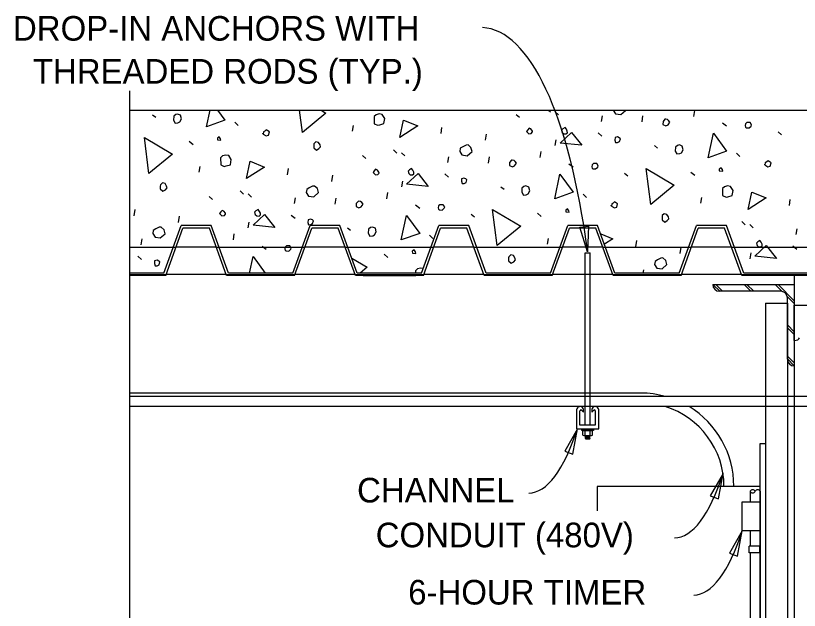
# Model space of a CAD drawing. Extents: x 927736.2 to 927809.6, y 636703.6 to 636757.7.
# Drawn here: x 927784.6 to 927796.47, y 636748.62 to 636757.62 of the extents above; entities that cross this region are included whole.
import ezdxf

# ---------------------------------------------------------------- set-up
doc = ezdxf.new("R2010")
doc.units = 0
for name, color, linetype in [('Default', 7, 'Continuous'), ('DimLines_dp', 7, 'Continuous'), ('Miscellaneous1', 7, 'Continuous'), ('Miscellaneous2', 7, 'Continuous'), ('Miscellaneous3', 7, 'Continuous')]:
    doc.layers.add(name, color=color, linetype=linetype)

msp = doc.modelspace()

# ---------------------------------------------------------------- linework, layer by layer
at = {"layer": 'Default'}
msp.add_line((927795.875, 636749.822), (927795.875, 636743.545), dxfattribs=at)
at = {"layer": 'DimLines_dp'}
msp.add_lwpolyline([(927786.333, 636737.782), (927786.333, 636747.055), (927786.142, 636747.055), (927786.333, 636747.139), (927786.524, 636747.222), (927786.333, 636747.222), (927786.333, 636756.484)], dxfattribs=at)
for points in [[(927793.262, 636754.047), (927793.144, 636754.42), (927793.273, 636754.438)], [(927793.108, 636751.368), (927792.915, 636751.028), (927793.038, 636750.984)], [(927795.311, 636750.689), (927795.118, 636750.349), (927795.241, 636750.305)], [(927795.602, 636749.822), (927795.409, 636749.483), (927795.532, 636749.438)]]:
    msp.add_lwpolyline(points, close=True, dxfattribs=at)
for centre, major_axis, ratio, start_param, end_param in [((927791.283, 636750.246), (-0.388, -7.199), 0.2923, 2.142822, 3.141563), ((927792.341, 636754.506), (-0.032, 4.113), 0.280094, 3.141615, 3.84244), ((927794.544, 636753.827), (-0.032, 4.113), 0.280094, 3.141615, 3.84244), ((927794.835, 636752.961), (-0.032, 4.113), 0.280094, 3.141615, 3.84244)]:
    msp.add_ellipse(centre, major_axis=major_axis, ratio=ratio, start_param=start_param, end_param=end_param, dxfattribs=at)
at = {"layer": 'Miscellaneous1'}
for p, q in [((927794.065, 636751.907), (927786.333, 636751.907)), ((927795.952, 636751.856), (927786.333, 636751.856)), ((927797.417, 636751.856), (927795.952, 636751.856)), ((927795.952, 636751.702), (927786.333, 636751.702)), ((927793.095, 636751.651), (927793.095, 636751.368)), ((927793.146, 636751.419), (927793.146, 636751.639)), ((927793.168, 636751.648), (927793.198, 636751.618)), ((927793.198, 636751.663), (927793.192, 636751.673)), ((927793.198, 636751.618), (927793.198, 636751.663)), ((927793.332, 636751.673), (927793.326, 636751.663)), ((927793.326, 636751.663), (927793.326, 636751.618)), ((927793.326, 636751.618), (927793.356, 636751.648)), ((927793.378, 636751.639), (927793.378, 636751.419)), ((927793.429, 636751.368), (927793.429, 636751.651)), ((927797.417, 636751.702), (927795.952, 636751.702)), ((927793.378, 636751.419), (927793.146, 636751.419)), ((927793.095, 636751.368), (927793.429, 636751.368)), ((927795.721, 636750.42), (927795.721, 636750.262)), ((927795.875, 636750.42), (927795.875, 636750.262)), ((927795.875, 636749.822), (927795.875, 636750.262)), ((927795.721, 636749.822), (927795.721, 636749.588)), ((927795.721, 636749.485), (927795.721, 636744.78))]:
    msp.add_line(p, q, dxfattribs=at)
msp.add_lwpolyline([(927795.875, 636743.771), (927795.875, 636750.493), (927793.408, 636750.493), (927793.408, 636750.124)], dxfattribs=at)
msp.add_lwpolyline([(927795.602, 636750.262), (927795.875, 636750.262), (927795.875, 636749.822), (927795.602, 636749.822)], close=True, dxfattribs=at)
for centre, radius, start, end in [((927794.065, 636750.497), 1.41, 74.4971, 90), ((927793.146, 636751.651), 0.0513, 26.1794, 179.9999), ((927793.159, 636751.639), 0.0128, 45, 180), ((927793.378, 636751.651), 0.0513, 0.0001, 153.8206), ((927793.365, 636751.639), 0.0128, 360, 135), ((927794.065, 636750.497), 1.26, 0, 72.9364), ((927794.065, 636750.497), 1.41, 0, 58.6817), ((927795.759, 636750.398), 0.0441, 29.0027, 150.9974), ((927795.836, 636750.398), 0.0441, 29.0028, 150.9973), ((927795.759, 636750.441), 0.0441, 209.003, 330.9971)]:
    msp.add_arc(centre, radius, start, end, dxfattribs=at)
at = {"layer": 'Miscellaneous2'}
for p, q in [((927786.333, 636756.193), (927803.622, 636756.193)), ((927786.677, 636756.123), (927786.725, 636756.085)), ((927792.178, 636756.129), (927792.228, 636756.085)), ((927792.67, 636756.193), (927792.698, 636756.166)), ((927792.767, 636756.172), (927792.819, 636756.122)), ((927794.868, 636756.096), (927794.882, 636756.189)), ((927787.92, 636756.009), (927787.972, 636755.959)), ((927793.471, 636756.022), (927793.486, 636756.109)), ((927794.086, 636756.014), (927794.099, 636756.107)), ((927795.302, 636756.002), (927795.366, 636755.955)), ((927789.705, 636755.875), (927789.72, 636755.962)), ((927791.043, 636755.838), (927791.057, 636755.931)), ((927791.715, 636755.737), (927791.729, 636755.83)), ((927793.422, 636755.849), (927793.479, 636755.801)), ((927796.144, 636755.864), (927796.194, 636755.819)), ((927787.231, 636755.723), (927787.289, 636755.674)), ((927792.771, 636755.656), (927792.786, 636755.743)), ((927794.272, 636755.656), (927794.32, 636755.617)), ((927790.324, 636755.594), (927790.375, 636755.544)), ((927790.444, 636755.549), (927790.496, 636755.499)), ((927792.545, 636755.474), (927792.559, 636755.567)), ((927795.515, 636755.542), (927795.567, 636755.492)), ((927789.855, 636755.506), (927789.905, 636755.462)), ((927791.148, 636755.4), (927791.163, 636755.487)), ((927791.763, 636755.392), (927791.776, 636755.485)), ((927787.382, 636755.252), (927787.397, 636755.339)), ((927788.72, 636755.215), (927788.734, 636755.308)), ((927792.979, 636755.379), (927793.043, 636755.333)), ((927789.392, 636755.114), (927789.406, 636755.207)), ((927791.099, 636755.227), (927791.156, 636755.178)), ((927793.821, 636755.241), (927793.871, 636755.197)), ((927794.826, 636755.255), (927794.883, 636755.207)), ((927790.448, 636755.033), (927790.463, 636755.12)), ((927788, 636754.971), (927788.052, 636754.921)), ((927790.222, 636754.851), (927790.236, 636754.944)), ((927791.948, 636755.033), (927791.997, 636754.995)), ((927787.532, 636754.884), (927787.582, 636754.84)), ((927788.121, 636754.927), (927788.173, 636754.877)), ((927788.825, 636754.777), (927788.84, 636754.864)), ((927789.44, 636754.769), (927789.453, 636754.862)), ((927793.192, 636754.919), (927793.244, 636754.869)), ((927794.977, 636754.785), (927794.992, 636754.872)), ((927796.315, 636754.748), (927796.329, 636754.84)), ((927790.656, 636754.757), (927790.72, 636754.71)), ((927786.397, 636754.593), (927786.411, 636754.686)), ((927787.069, 636754.492), (927787.083, 636754.585)), ((927788.775, 636754.604), (927788.833, 636754.556)), ((927791.498, 636754.619), (927791.548, 636754.575)), ((927792.503, 636754.633), (927792.56, 636754.584)), ((927788.125, 636754.411), (927788.14, 636754.498)), ((927795.595, 636754.504), (927795.647, 636754.454)), ((927795.716, 636754.459), (927795.767, 636754.409)), ((927786.849, 636753.726), (927787.111, 636754.446)), ((927786.876, 636753.688), (927787.137, 636754.407)), ((927787.563, 636754.446), (927787.111, 636754.446)), ((927787.536, 636754.407), (927787.137, 636754.407)), ((927787.798, 636753.688), (927787.536, 636754.407)), ((927787.825, 636753.726), (927787.563, 636754.446)), ((927788.798, 636753.726), (927789.06, 636754.446)), ((927788.825, 636753.688), (927789.087, 636754.407)), ((927789.512, 636754.446), (927789.06, 636754.446)), ((927789.485, 636754.407), (927789.087, 636754.407)), ((927789.747, 636753.688), (927789.485, 636754.407)), ((927789.774, 636753.726), (927789.512, 636754.446)), ((927789.625, 636754.411), (927789.674, 636754.373)), ((927790.748, 636753.726), (927791.01, 636754.446)), ((927790.775, 636753.688), (927791.037, 636754.407)), ((927791.462, 636754.446), (927791.01, 636754.446)), ((927791.435, 636754.407), (927791.037, 636754.407)), ((927791.697, 636753.688), (927791.435, 636754.407)), ((927791.724, 636753.726), (927791.462, 636754.446)), ((927792.698, 636753.726), (927792.96, 636754.446)), ((927792.725, 636753.688), (927792.987, 636754.407)), ((927793.412, 636754.446), (927792.96, 636754.446)), ((927793.385, 636754.407), (927792.987, 636754.407)), ((927793.647, 636753.688), (927793.385, 636754.407)), ((927793.674, 636753.726), (927793.412, 636754.446)), ((927794.648, 636753.726), (927794.91, 636754.446)), ((927794.675, 636753.688), (927794.936, 636754.407)), ((927795.362, 636754.446), (927794.91, 636754.446)), ((927795.335, 636754.407), (927794.936, 636754.407)), ((927795.597, 636753.688), (927795.335, 636754.407)), ((927795.624, 636753.726), (927795.362, 636754.446)), ((927796.42, 636754.309), (927796.435, 636754.397)), ((927786.502, 636754.155), (927786.517, 636754.242)), ((927787.899, 636754.229), (927787.913, 636754.322)), ((927790.869, 636754.297), (927790.921, 636754.247)), ((927792.654, 636754.162), (927792.669, 636754.249)), ((927788.333, 636754.135), (927788.397, 636754.088)), ((927793.992, 636754.125), (927794.005, 636754.218)), ((927794.664, 636754.024), (927794.677, 636754.117)), ((927796.37, 636754.137), (927796.428, 636754.088)), ((927786.452, 636753.982), (927786.51, 636753.933)), ((927790.18, 636754.01), (927790.237, 636753.962)), ((927795.72, 636753.943), (927795.735, 636754.03)), ((927794.103, 636753.726), (927794.112, 636753.774)), ((927786.849, 636753.726), (927786.333, 636753.726)), ((927786.876, 636753.688), (927786.333, 636753.688)), ((927788.825, 636753.688), (927787.798, 636753.688)), ((927788.798, 636753.726), (927787.825, 636753.726)), ((927790.775, 636753.688), (927789.747, 636753.688)), ((927790.748, 636753.726), (927789.774, 636753.726)), ((927789.863, 636753.688), (927790.659, 636753.688)), ((927792.725, 636753.688), (927791.697, 636753.688)), ((927792.698, 636753.726), (927791.724, 636753.726)), ((927792.622, 636753.688), (927791.8, 636753.688)), ((927794.675, 636753.688), (927793.647, 636753.688)), ((927794.648, 636753.726), (927793.674, 636753.726)), ((927796.624, 636753.688), (927795.597, 636753.688)), ((927796.597, 636753.726), (927795.624, 636753.726))]:
    msp.add_line(p, q, dxfattribs=at)
for points in [[(927786.996, 636756.1), (927786.992, 636756.042), (927787.017, 636755.997), (927787.06, 636756.002), (927787.088, 636756.016), (927787.115, 636756.062), (927787.1, 636756.115), (927787.056, 636756.135), (927787.027, 636756.127), (927786.996, 636756.1)], [(927787.492, 636755.939), (927787.546, 636756.193)], [(927787.659, 636756.193), (927787.772, 636756.04), (927787.492, 636755.939)], [(927788.944, 636755.856), (927788.902, 636756.193)], [(927789.226, 636756.193), (927789.3, 636756.149), (927788.944, 636755.856)], [(927790.029, 636756.096), (927790.033, 636755.988), (927790.084, 636755.964), (927790.114, 636755.971), (927790.179, 636755.989), (927790.19, 636756.069), (927790.154, 636756.129), (927790.108, 636756.136), (927790.06, 636756.123), (927790.029, 636756.096)], [(927793.649, 636756.191), (927793.683, 636756.136), (927793.762, 636756.126), (927793.835, 636756.19), (927793.834, 636756.193)], [(927793.649, 636756.193), (927793.649, 636756.191)], [(927790.421, 636755.779), (927790.477, 636756.043), (927790.693, 636755.954), (927790.421, 636755.779)], [(927794.403, 636756.023), (927794.402, 636755.978), (927794.446, 636755.958), (927794.48, 636755.973), (927794.508, 636756.013), (927794.488, 636756.039), (927794.471, 636756.054), (927794.444, 636756.059), (927794.432, 636756.056), (927794.403, 636756.023)], [(927795.652, 636755.936), (927795.667, 636755.927), (927795.706, 636755.925), (927795.737, 636755.952), (927795.744, 636755.973), (927795.723, 636756.006), (927795.672, 636756.005), (927795.651, 636755.987), (927795.646, 636755.96), (927795.652, 636755.936)], [(927788.351, 636755.831), (927788.396, 636755.805), (927788.432, 636755.815), (927788.445, 636755.863), (927788.398, 636755.895), (927788.377, 636755.876), (927788.355, 636755.864), (927788.351, 636755.831), (927788.348, 636755.843)], [(927792.337, 636755.871), (927792.372, 636755.836), (927792.409, 636755.84), (927792.428, 636755.864), (927792.425, 636755.876), (927792.403, 636755.908), (927792.375, 636755.92), (927792.356, 636755.896), (927792.337, 636755.871)], [(927792.877, 636755.856), (927792.901, 636755.837), (927792.934, 636755.833), (927792.955, 636755.852), (927792.954, 636755.877), (927792.94, 636755.905), (927792.921, 636755.932), (927792.888, 636755.91), (927792.867, 636755.892), (927792.877, 636755.856)], [(927786.621, 636755.234), (927786.552, 636755.777), (927786.977, 636755.527), (927786.621, 636755.234)], [(927787.66, 636755.742), (927787.712, 636755.737), (927787.706, 636755.76), (927787.686, 636755.787), (927787.659, 636755.767), (927787.66, 636755.742)], [(927792.844, 636755.694), (927793.018, 636755.856), (927793.172, 636755.661), (927792.844, 636755.694)], [(927793.675, 636755.738), (927793.684, 636755.702), (927793.716, 636755.705), (927793.744, 636755.718), (927793.758, 636755.761), (927793.741, 636755.775), (927793.713, 636755.787), (927793.677, 636755.777), (927793.675, 636755.738)], [(927795.087, 636755.472), (927795.166, 636755.844), (927795.366, 636755.572), (927795.087, 636755.472)], [(927789.117, 636755.666), (927789.116, 636755.621), (927789.157, 636755.587), (927789.195, 636755.611), (927789.22, 636755.636), (927789.212, 636755.666), (927789.189, 636755.705), (927789.149, 636755.713), (927789.118, 636755.685), (927789.117, 636755.666)], [(927791.326, 636755.569), (927791.36, 636755.514), (927791.439, 636755.503), (927791.512, 636755.567), (927791.496, 636755.627), (927791.453, 636755.666), (927791.422, 636755.664), (927791.371, 636755.638), (927791.333, 636755.615), (927791.326, 636755.569)], [(927794.591, 636755.632), (927794.587, 636755.574), (927794.612, 636755.53), (927794.655, 636755.535), (927794.683, 636755.549), (927794.709, 636755.594), (927794.695, 636755.648), (927794.651, 636755.668), (927794.621, 636755.66), (927794.591, 636755.632)], [(927787.706, 636755.473), (927787.71, 636755.366), (927787.761, 636755.341), (927787.791, 636755.349), (927787.856, 636755.367), (927787.867, 636755.446), (927787.831, 636755.507), (927787.785, 636755.513), (927787.737, 636755.501), (927787.706, 636755.473)], [(927788.098, 636755.157), (927788.154, 636755.421), (927788.37, 636755.332), (927788.098, 636755.157)], [(927792.08, 636755.4), (927792.079, 636755.355), (927792.123, 636755.335), (927792.157, 636755.351), (927792.185, 636755.39), (927792.165, 636755.417), (927792.148, 636755.431), (927792.121, 636755.437), (927792.109, 636755.434), (927792.08, 636755.4)], [(927795.946, 636755.364), (927795.991, 636755.337), (927796.027, 636755.347), (927796.039, 636755.395), (927795.993, 636755.427), (927795.972, 636755.409), (927795.95, 636755.397), (927795.946, 636755.364), (927795.943, 636755.375)], [(927790.014, 636755.249), (927790.049, 636755.214), (927790.086, 636755.217), (927790.105, 636755.241), (927790.102, 636755.253), (927790.08, 636755.286), (927790.052, 636755.297), (927790.033, 636755.273), (927790.014, 636755.249)], [(927790.554, 636755.234), (927790.578, 636755.215), (927790.611, 636755.211), (927790.632, 636755.229), (927790.631, 636755.255), (927790.617, 636755.283), (927790.598, 636755.309), (927790.565, 636755.288), (927790.544, 636755.27), (927790.554, 636755.234)], [(927793.329, 636755.314), (927793.344, 636755.305), (927793.383, 636755.303), (927793.414, 636755.33), (927793.421, 636755.351), (927793.4, 636755.384), (927793.349, 636755.383), (927793.328, 636755.364), (927793.323, 636755.337), (927793.329, 636755.314)], [(927794.216, 636754.766), (927794.147, 636755.309), (927794.572, 636755.059), (927794.216, 636754.766)], [(927795.255, 636755.274), (927795.307, 636755.269), (927795.301, 636755.293), (927795.281, 636755.319), (927795.254, 636755.3), (927795.255, 636755.274)], [(927790.521, 636755.072), (927790.695, 636755.233), (927790.849, 636755.038), (927790.521, 636755.072)], [(927792.764, 636754.849), (927792.843, 636755.222), (927793.043, 636754.95), (927792.764, 636754.849)], [(927786.794, 636755.044), (927786.793, 636754.999), (927786.834, 636754.965), (927786.872, 636754.988), (927786.897, 636755.014), (927786.889, 636755.044), (927786.866, 636755.082), (927786.826, 636755.09), (927786.795, 636755.063), (927786.794, 636755.044)], [(927791.352, 636755.116), (927791.361, 636755.08), (927791.393, 636755.082), (927791.421, 636755.096), (927791.435, 636755.138), (927791.418, 636755.153), (927791.39, 636755.164), (927791.354, 636755.155), (927791.352, 636755.116)], [(927789.003, 636754.946), (927789.037, 636754.891), (927789.116, 636754.881), (927789.189, 636754.945), (927789.173, 636755.004), (927789.13, 636755.044), (927789.099, 636755.042), (927789.048, 636755.016), (927789.01, 636754.993), (927789.003, 636754.946)], [(927792.267, 636755.01), (927792.264, 636754.952), (927792.289, 636754.907), (927792.332, 636754.912), (927792.36, 636754.926), (927792.386, 636754.972), (927792.372, 636755.025), (927792.328, 636755.045), (927792.298, 636755.037), (927792.267, 636755.01)], [(927795.301, 636755.006), (927795.304, 636754.898), (927795.356, 636754.873), (927795.385, 636754.881), (927795.451, 636754.899), (927795.462, 636754.978), (927795.426, 636755.039), (927795.38, 636755.046), (927795.332, 636755.033), (927795.301, 636755.006)], [(927795.692, 636754.689), (927795.749, 636754.953), (927795.965, 636754.864), (927795.692, 636754.689)], [(927789.757, 636754.778), (927789.756, 636754.733), (927789.8, 636754.713), (927789.834, 636754.728), (927789.862, 636754.768), (927789.842, 636754.794), (927789.825, 636754.809), (927789.798, 636754.814), (927789.786, 636754.811), (927789.757, 636754.778)], [(927791.006, 636754.691), (927791.021, 636754.682), (927791.06, 636754.68), (927791.091, 636754.707), (927791.098, 636754.729), (927791.076, 636754.761), (927791.026, 636754.76), (927791.005, 636754.742), (927790.999, 636754.715), (927791.006, 636754.691)], [(927792.932, 636754.652), (927792.984, 636754.647), (927792.978, 636754.67), (927792.958, 636754.697), (927792.931, 636754.677), (927792.932, 636754.652)], [(927793.623, 636754.741), (927793.668, 636754.715), (927793.704, 636754.725), (927793.716, 636754.773), (927793.67, 636754.805), (927793.649, 636754.786), (927793.627, 636754.774), (927793.623, 636754.741), (927793.62, 636754.753)], [(927787.691, 636754.626), (927787.726, 636754.591), (927787.763, 636754.595), (927787.782, 636754.619), (927787.779, 636754.631), (927787.757, 636754.663), (927787.729, 636754.675), (927787.71, 636754.651), (927787.691, 636754.626)], [(927788.198, 636754.449), (927788.372, 636754.611), (927788.526, 636754.416), (927788.198, 636754.449)], [(927788.231, 636754.612), (927788.255, 636754.592), (927788.288, 636754.589), (927788.309, 636754.607), (927788.308, 636754.632), (927788.294, 636754.66), (927788.274, 636754.687), (927788.242, 636754.666), (927788.221, 636754.647), (927788.231, 636754.612)], [(927790.441, 636754.227), (927790.52, 636754.599), (927790.72, 636754.327), (927790.441, 636754.227)], [(927791.893, 636754.144), (927791.824, 636754.687), (927792.249, 636754.437), (927791.893, 636754.144)], [(927794.388, 636754.576), (927794.388, 636754.531), (927794.429, 636754.497), (927794.467, 636754.52), (927794.492, 636754.546), (927794.484, 636754.576), (927794.461, 636754.615), (927794.421, 636754.623), (927794.39, 636754.595), (927794.388, 636754.576)], [(927789.029, 636754.493), (927789.038, 636754.458), (927789.07, 636754.46), (927789.098, 636754.474), (927789.112, 636754.516), (927789.095, 636754.53), (927789.067, 636754.542), (927789.031, 636754.532), (927789.029, 636754.493)], [(927786.68, 636754.324), (927786.714, 636754.269), (927786.793, 636754.258), (927786.866, 636754.322), (927786.85, 636754.382), (927786.807, 636754.422), (927786.776, 636754.419), (927786.725, 636754.393), (927786.687, 636754.37), (927786.68, 636754.324)], [(927789.944, 636754.388), (927789.941, 636754.329), (927789.966, 636754.285), (927790.009, 636754.29), (927790.037, 636754.304), (927790.063, 636754.349), (927790.049, 636754.403), (927790.005, 636754.423), (927789.975, 636754.415), (927789.944, 636754.388)], [(927793.459, 636754.318), (927793.642, 636754.242), (927793.516, 636754.161)], [(927795.826, 636754.144), (927795.85, 636754.125), (927795.883, 636754.121), (927795.904, 636754.139), (927795.903, 636754.165), (927795.889, 636754.193), (927795.869, 636754.219), (927795.837, 636754.198), (927795.816, 636754.18), (927795.826, 636754.144)], [(927788.683, 636754.069), (927788.698, 636754.06), (927788.737, 636754.058), (927788.768, 636754.085), (927788.775, 636754.106), (927788.753, 636754.139), (927788.703, 636754.138), (927788.682, 636754.119), (927788.676, 636754.092), (927788.683, 636754.069)], [(927795.793, 636753.982), (927795.966, 636754.143), (927796.121, 636753.948), (927795.793, 636753.982)], [(927790.609, 636754.029), (927790.661, 636754.024), (927790.655, 636754.048), (927790.635, 636754.075), (927790.608, 636754.055), (927790.609, 636754.029)], [(927792.065, 636753.954), (927792.065, 636753.909), (927792.106, 636753.875), (927792.144, 636753.898), (927792.169, 636753.924), (927792.161, 636753.954), (927792.138, 636753.992), (927792.097, 636754), (927792.067, 636753.973), (927792.065, 636753.954)], [(927786.706, 636753.871), (927786.715, 636753.835), (927786.747, 636753.837), (927786.775, 636753.851), (927786.789, 636753.893), (927786.772, 636753.908), (927786.744, 636753.919), (927786.708, 636753.91), (927786.706, 636753.871)], [(927788.144, 636753.726), (927788.197, 636753.977), (927788.382, 636753.726)], [(927789.692, 636753.952), (927789.926, 636753.814), (927789.819, 636753.726)], [(927794.275, 636753.856), (927794.309, 636753.801), (927794.388, 636753.791), (927794.46, 636753.855), (927794.444, 636753.914), (927794.402, 636753.954), (927794.37, 636753.952), (927794.32, 636753.926), (927794.282, 636753.903), (927794.275, 636753.856)], [(927790.773, 636753.795), (927790.734, 636753.801), (927790.686, 636753.788), (927790.655, 636753.761)], [(927790.655, 636753.761), (927790.656, 636753.726)]]:
    msp.add_lwpolyline(points, dxfattribs=at)
at = {"layer": 'Miscellaneous3'}
for p, q in [((927786.333, 636754.118), (927787.032, 636754.118)), ((927787.641, 636754.118), (927787.032, 636754.118)), ((927787.641, 636754.118), (927788.982, 636754.118)), ((927789.591, 636754.118), (927788.982, 636754.118)), ((927789.591, 636754.118), (927790.932, 636754.118)), ((927791.541, 636754.118), (927790.932, 636754.118)), ((927791.541, 636754.118), (927792.881, 636754.118)), ((927793.49, 636754.118), (927792.881, 636754.118)), ((927793.49, 636754.118), (927794.831, 636754.118)), ((927795.44, 636754.118), (927794.831, 636754.118)), ((927795.44, 636754.118), (927796.781, 636754.118)), ((927793.224, 636751.419), (927793.224, 636754.034)), ((927793.224, 636754.034), (927793.301, 636754.034)), ((927793.301, 636751.419), (927793.301, 636754.034)), ((927786.333, 636753.706), (927786.882, 636753.706)), ((927787.791, 636753.706), (927786.882, 636753.706)), ((927787.791, 636753.706), (927788.832, 636753.706)), ((927789.741, 636753.706), (927788.832, 636753.706)), ((927789.741, 636753.706), (927790.782, 636753.706)), ((927791.69, 636753.706), (927790.782, 636753.706)), ((927791.69, 636753.706), (927792.732, 636753.706)), ((927793.64, 636753.706), (927792.732, 636753.706)), ((927793.64, 636753.706), (927794.681, 636753.706)), ((927795.59, 636753.706), (927794.681, 636753.706)), ((927795.59, 636753.706), (927796.631, 636753.706)), ((927796.389, 636753.706), (927796.389, 636753.552)), ((927795.155, 636753.552), (927796.389, 636753.552)), ((927795.261, 636753.449), (927795.158, 636753.552)), ((927795.305, 636753.449), (927795.202, 636753.552)), ((927795.732, 636753.449), (927795.629, 636753.552)), ((927795.776, 636753.449), (927795.673, 636753.552)), ((927796.209, 636753.443), (927796.1, 636753.552)), ((927796.389, 636753.307), (927796.144, 636753.552)), ((927796.389, 636753.552), (927796.389, 636752.319)), ((927796.183, 636753.449), (927795.258, 636753.449)), ((927796.389, 636753.264), (927796.279, 636753.373)), ((927796.286, 636752.422), (927796.286, 636753.347)), ((927795.952, 636753.27), (927795.952, 636751.141)), ((927795.952, 636753.27), (927796.286, 636753.27)), ((927796.286, 636753.27), (927796.286, 636742.324)), ((927796.389, 636752.705), (927796.389, 636753.237)), ((927796.389, 636753.237), (927797.417, 636753.237)), ((927796.389, 636752.836), (927796.286, 636752.939)), ((927796.389, 636752.793), (927796.286, 636752.896)), ((927796.389, 636752.365), (927796.286, 636752.468)), ((927796.389, 636752.322), (927796.286, 636752.425)), ((927796.389, 636752.319), (927796.389, 636740.268)), ((927793.188, 636751.271), (927793.188, 636751.341)), ((927793.188, 636751.341), (927793.336, 636751.341)), ((927793.206, 636751.265), (927793.318, 636751.265)), ((927793.223, 636751.264), (927793.24, 636751.265)), ((927793.223, 636751.264), (927793.226, 636751.265)), ((927793.236, 636751.258), (927793.223, 636751.264)), ((927793.223, 636751.251), (927793.236, 636751.258)), ((927793.223, 636751.251), (927793.3, 636751.257)), ((927793.225, 636751.271), (927793.225, 636751.341)), ((927793.287, 636751.263), (927793.291, 636751.265)), ((927793.3, 636751.257), (927793.287, 636751.263)), ((927793.287, 636751.25), (927793.3, 636751.257)), ((927793.299, 636751.271), (927793.299, 636751.341)), ((927793.336, 636751.271), (927793.336, 636751.341)), ((927793.236, 636751.245), (927793.223, 636751.251)), ((927793.223, 636751.238), (927793.3, 636751.245)), ((927793.223, 636751.238), (927793.236, 636751.245)), ((927793.236, 636751.233), (927793.223, 636751.238)), ((927793.223, 636751.225), (927793.236, 636751.233)), ((927793.223, 636751.225), (927793.3, 636751.232)), ((927793.236, 636751.22), (927793.223, 636751.225)), ((927793.228, 636751.215), (927793.236, 636751.22)), ((927793.228, 636751.215), (927793.293, 636751.215)), ((927793.253, 636751.215), (927793.3, 636751.219)), ((927793.3, 636751.245), (927793.287, 636751.25)), ((927793.287, 636751.237), (927793.3, 636751.245)), ((927793.3, 636751.232), (927793.287, 636751.237)), ((927793.287, 636751.224), (927793.3, 636751.232)), ((927793.3, 636751.219), (927793.287, 636751.224)), ((927793.293, 636751.215), (927793.3, 636751.219)), ((927795.875, 636749.588), (927795.708, 636749.588)), ((927795.708, 636749.485), (927795.708, 636749.588)), ((927795.875, 636749.485), (927795.708, 636749.485)), ((927795.862, 636749.588), (927795.862, 636749.485))]:
    msp.add_line(p, q, dxfattribs=at)
for points in [[(927793.349, 636751.368), (927793.349, 636751.341), (927793.175, 636751.341), (927793.175, 636751.368)], [(927795.875, 636751.141), (927795.952, 636751.141), (927795.952, 636743.124), (927795.875, 636743.124)]]:
    msp.add_lwpolyline(points, close=True, dxfattribs=at)
for centre, radius, start, end in [((927795.258, 636753.552), 0.103, 180, 270), ((927796.183, 636753.347), 0.103, 0, 90), ((927796.389, 636752.422), 0.103, 180, 270), ((927793.206, 636751.299), 0.034, 236.9791, 303.0209), ((927793.262, 636751.393), 0.128, 253.1396, 286.8604), ((927793.318, 636751.299), 0.034, 236.9791, 303.0209)]:
    msp.add_arc(centre, radius, start, end, dxfattribs=at)
msp.add_ellipse((927796.389, 636752.744), major_axis=(0.0771, 0), ratio=0.5176, start_param=4.712389, end_param=6.283185, dxfattribs=at)

# ---------------------------------------------------------------- texts
at = {"layer": 'DimLines_dp'}
for s, height, p in [('DROP-IN ANCHORS WITH', 0.37296, (927784.564, 636757.246)), ('THREADED RODS (TYP.)', 0.37296, (927784.865, 636756.595)), ('CHANNEL', 0.373, (927789.772, 636750.25)), ('CONDUIT (480V)', 0.37296, (927790.054, 636749.571)), ('6-HOUR TIMER', 0.37296, (927790.546, 636748.704))]:
    msp.add_text(s, height=height, dxfattribs=at).set_placement(p)

doc.saveas('drawing.dxf')
